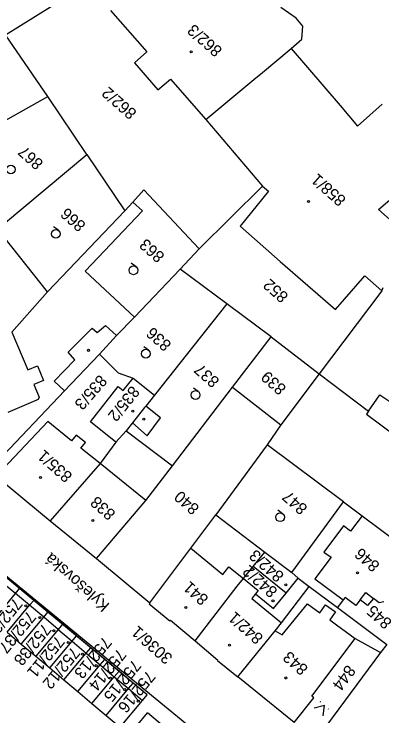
# Model space of a CAD drawing. Extents: x -496688 to -495455, y -1089309 to -1088026.
# Drawn here: x -496161.2 to -496098.1, y -1088339.8 to -1088219.5 of the extents above; entities that cross this region are included whole.
import ezdxf

# ---------------------------------------------------------------- set-up
doc = ezdxf.new("R2010")
doc.units = 0
for name, color, linetype in [('Vrstva 23', 7, 'Continuous'), ('Vrstva 52', 7, 'Continuous'), ('Vrstva 53', 7, 'Continuous'), ('Vrstva 55', 7, 'Continuous'), ('Vrstva 56', 7, 'Continuous'), ('Vrstva 57', 7, 'Continuous'), ('Vrstva 58', 7, 'Continuous'), ('Vrstva 59', 7, 'Continuous')]:
    doc.layers.add(name, color=color, linetype=linetype)

msp = doc.modelspace()

# ---------------------------------------------------------------- linework, layer by layer
at = {"layer": 'Vrstva 23'}
for p, q in [((-496112.79, -1088220.23), (-496115.42, -1088218.43)), ((-496144.6, -1088218.93), (-496138.4, -1088226.02)), ((-496111.62, -1088221.6), (-496112.79, -1088220.23)), ((-496111.79, -1088223.84), (-496111.62, -1088221.6)), ((-496113.66, -1088225.45), (-496111.79, -1088223.84)), ((-496118.91, -1088229.82), (-496113.66, -1088225.45)), ((-496113.66, -1088225.45), (-496105.26, -1088235.24)), ((-496128.26, -1088237.61), (-496119.69, -1088230.47)), ((-496119.69, -1088230.47), (-496118.91, -1088229.82)), ((-496134.32, -1088230.68), (-496128.26, -1088237.61)), ((-496105.26, -1088235.24), (-496102.26, -1088238.74)), ((-496102.26, -1088238.74), (-496098.04, -1088234.96)), ((-496128.26, -1088237.61), (-496118.54, -1088249.02)), ((-496098.65, -1088253.06), (-496092.09, -1088247.31)), ((-496118.54, -1088249.02), (-496117.55, -1088249.89)), ((-496092.23, -1088258.76), (-496098.65, -1088253.06)), ((-496098.08, -1088266.98), (-496100.99, -1088264.42)), ((-496098.08, -1088266.98), (-496097.87, -1088266.38)), ((-496147.73, -1088273.39), (-496146.88, -1088274.11)), ((-496146.88, -1088274.11), (-496145.47, -1088272.9)), ((-496145.47, -1088272.9), (-496143.57, -1088274.63)), ((-496161.51, -1088274.08), (-496158.8, -1088280.53)), ((-496146.52, -1088277.8), (-496143.57, -1088274.63)), ((-496150.7, -1088278.8), (-496151.86, -1088277.47)), ((-496148.95, -1088280.41), (-496146.52, -1088277.8)), ((-496158.8, -1088280.53), (-496157.14, -1088279.83)), ((-496154.26, -1088282.46), (-496150.7, -1088278.8)), ((-496142.42, -1088284.07), (-496140.75, -1088281.96)), ((-496140.75, -1088281.96), (-496137.09, -1088284.86)), ((-496156.09, -1088282.34), (-496157.75, -1088283.04)), ((-496157.75, -1088283.04), (-496156.84, -1088285.21)), ((-496152.52, -1088284.11), (-496154.26, -1088282.46)), ((-496148.07, -1088289.43), (-496143.32, -1088283.36)), ((-496143.32, -1088283.36), (-496142.42, -1088284.07)), ((-496157.03, -1088285.58), (-496162.2, -1088287.82)), ((-496137.09, -1088284.86), (-496138.57, -1088286.73)), ((-496100.39, -1088287.57), (-496098.46, -1088284.79)), ((-496098.46, -1088284.79), (-496093.56, -1088288.08)), ((-496138.76, -1088286.97), (-496140.84, -1088289.57)), ((-496138.57, -1088286.73), (-496138.76, -1088286.97)), ((-496136.04, -1088288.75), (-496138.57, -1088286.73)), ((-496100.39, -1088287.57), (-496100.74, -1088288.08)), ((-496100.74, -1088288.08), (-496095.56, -1088291.95)), ((-496155.37, -1088289.39), (-496164.02, -1088298.48)), ((-496151.28, -1088292.67), (-496155.37, -1088289.39)), ((-496143.68, -1088292.88), (-496148.07, -1088289.43)), ((-496140.84, -1088289.57), (-496141.93, -1088290.94)), ((-496140.84, -1088289.57), (-496138.33, -1088291.8)), ((-496150.49, -1088291.68), (-496151.28, -1088292.67)), ((-496148.9, -1088292.95), (-496150.49, -1088291.68)), ((-496141.93, -1088290.94), (-496143.68, -1088292.88)), ((-496149.69, -1088293.94), (-496148.9, -1088292.95)), ((-496146.4, -1088296.58), (-496149.69, -1088293.94)), ((-496146.4, -1088296.58), (-496154.95, -1088306.41)), ((-496164.23, -1088298.7), (-496154.95, -1088306.41)), ((-496147.01, -1088312.86), (-496138.54, -1088302.87)), ((-496101.47, -1088305.51), (-496103.46, -1088308.16)), ((-496101.47, -1088305.51), (-496092.02, -1088312.57)), ((-496154.95, -1088306.41), (-496147.01, -1088312.86)), ((-496103.46, -1088308.16), (-496104.69, -1088307.24)), ((-496137.88, -1088320.43), (-496130.83, -1088311.08)), ((-496120.16, -1088314.21), (-496118.15, -1088311.73)), ((-496118.15, -1088311.73), (-496113.5, -1088315.25)), ((-496108.02, -1088311.73), (-496106.81, -1088312.63)), ((-496106.81, -1088312.63), (-496109.56, -1088316.31)), ((-496125.37, -1088315.57), (-496124.3, -1088314.26)), ((-496124.3, -1088314.26), (-496121.81, -1088316.24)), ((-496121.81, -1088316.24), (-496120.16, -1088314.21)), ((-496114.51, -1088318.76), (-496120.16, -1088314.21)), ((-496113.5, -1088315.25), (-496112.44, -1088316.23)), ((-496160.91, -1088318.84), (-496163.33, -1088316.82)), ((-496122.92, -1088317.59), (-496121.81, -1088316.24)), ((-496121.81, -1088316.24), (-496119.27, -1088318.32)), ((-496114.51, -1088318.76), (-496112.44, -1088316.23)), ((-496109.56, -1088316.31), (-496104.72, -1088319.89)), ((-496160.91, -1088318.84), (-496160.21, -1088317.99)), ((-496130.12, -1088326.92), (-496122.92, -1088317.59)), ((-496119.27, -1088318.32), (-496119.73, -1088318.87)), ((-496164.73, -1088323.45), (-496160.91, -1088318.84)), ((-496158.49, -1088320.86), (-496160.91, -1088318.84)), ((-496119.73, -1088318.87), (-496120.38, -1088319.67)), ((-496119.73, -1088318.87), (-496116.67, -1088321.39)), ((-496116.67, -1088321.39), (-496114.51, -1088318.76)), ((-496104.41, -1088319.49), (-496104.72, -1088319.89)), ((-496102.56, -1088320.89), (-496104.41, -1088319.49)), ((-496101.83, -1088319.94), (-496100.85, -1088318.64)), ((-496158.49, -1088320.86), (-496157.78, -1088320.01)), ((-496137.88, -1088320.43), (-496138.01, -1088320.62)), ((-496138.01, -1088320.62), (-496134.44, -1088323.53)), ((-496115.16, -1088325.93), (-496110.83, -1088320.6)), ((-496110.83, -1088320.6), (-496108.74, -1088322.12)), ((-496108.74, -1088322.12), (-496107.74, -1088320.75)), ((-496107.74, -1088320.75), (-496106.03, -1088321.99)), ((-496101.83, -1088319.94), (-496102.56, -1088320.89)), ((-496100.53, -1088320.88), (-496101.83, -1088319.94)), ((-496099.52, -1088319.68), (-496100.53, -1088320.88)), ((-496098.57, -1088320.43), (-496099.52, -1088319.68)), ((-496097.76, -1088320.27), (-496098.57, -1088320.43)), ((-496162.32, -1088325.48), (-496158.49, -1088320.86)), ((-496156.07, -1088322.89), (-496158.49, -1088320.86)), ((-496159.9, -1088327.5), (-496156.07, -1088322.89)), ((-496156.07, -1088322.89), (-496155.35, -1088322.02)), ((-496153.6, -1088325.01), (-496156.07, -1088322.89)), ((-496106.21, -1088322.23), (-496107.03, -1088323.37)), ((-496152.84, -1088324.11), (-496153.6, -1088325.01)), ((-496134.44, -1088323.53), (-496134.33, -1088323.4)), ((-496134.33, -1088323.4), (-496130.12, -1088326.92)), ((-496107.03, -1088323.37), (-496105.88, -1088324.2)), ((-496162.32, -1088325.48), (-496159.9, -1088327.5)), ((-496153.6, -1088325.01), (-496157.42, -1088329.57)), ((-496153.6, -1088325.01), (-496151.21, -1088327.02)), ((-496122.78, -1088333.12), (-496116.38, -1088325.22)), ((-496116.38, -1088325.22), (-496115.16, -1088325.93)), ((-496151.21, -1088327.02), (-496150.42, -1088326.11)), ((-496110.07, -1088336.41), (-496102.69, -1088326.52)), ((-496159.9, -1088327.5), (-496157.42, -1088329.57)), ((-496155.02, -1088331.59), (-496151.21, -1088327.02)), ((-496151.21, -1088327.02), (-496148.78, -1088329.06)), ((-496130.12, -1088326.92), (-496126.19, -1088330.23)), ((-496152.6, -1088333.64), (-496148.78, -1088329.06)), ((-496148.78, -1088329.06), (-496147.99, -1088328.13)), ((-496148.78, -1088329.06), (-496146.38, -1088331.07)), ((-496157.42, -1088329.57), (-496155.02, -1088331.59)), ((-496146.38, -1088331.07), (-496145.58, -1088330.13)), ((-496126.19, -1088330.23), (-496126.29, -1088330.34)), ((-496126.29, -1088330.34), (-496123.28, -1088332.72)), ((-496155.02, -1088331.59), (-496152.6, -1088333.64)), ((-496150.21, -1088335.65), (-496146.38, -1088331.07)), ((-496146.38, -1088331.07), (-496143.97, -1088333.1)), ((-496143.97, -1088333.1), (-496143.15, -1088332.15)), ((-496123.28, -1088332.72), (-496122.78, -1088333.12)), ((-496152.6, -1088333.64), (-496150.21, -1088335.65)), ((-496147.79, -1088337.68), (-496143.97, -1088333.1)), ((-496143.97, -1088333.1), (-496141.55, -1088335.13)), ((-496113.14, -1088340.92), (-496122.78, -1088333.12)), ((-496145.37, -1088339.71), (-496141.55, -1088335.13)), ((-496141.55, -1088335.13), (-496140.72, -1088334.17)), ((-496141.55, -1088335.13), (-496139.15, -1088337.15)), ((-496150.21, -1088335.65), (-496147.79, -1088337.68)), ((-496139.15, -1088337.15), (-496138.32, -1088336.17)), ((-496142.97, -1088341.74), (-496139.15, -1088337.15)), ((-496113.14, -1088340.92), (-496109.74, -1088336.7)), ((-496109.74, -1088336.7), (-496110.07, -1088336.41)), ((-496147.79, -1088337.68), (-496145.37, -1088339.71)), ((-496145.37, -1088339.71), (-496142.97, -1088341.74))]:
    msp.add_line(p, q, dxfattribs=at)
for points in [[(-496138.4, -1088226.02), (-496140.48, -1088227.9), (-496136.51, -1088232.52), (-496134.32, -1088230.68)], [(-496117.55, -1088249.89), (-496122.37, -1088255.87), (-496115.51, -1088261.93), (-496106.03, -1088270.19), (-496100.99, -1088264.42)], [(-496170.807, -1088309.208), (-496138.345, -1088336.158)], [(-496142.065, -1088343.835), (-496138.252, -1088339.268)], [(-496104.453, -1088367.769), (-496138.252, -1088339.268)]]:
    msp.add_lwpolyline(points, dxfattribs=at)
at = {"layer": 'Vrstva 52'}
for p, q in [((-496151.86, -1088277.47), (-496147.73, -1088273.39)), ((-496138.33, -1088291.8), (-496136.04, -1088288.75)), ((-496138.54, -1088302.87), (-496146.4, -1088296.58)), ((-496130.83, -1088311.08), (-496125.37, -1088315.57)), ((-496100.85, -1088318.64), (-496099.52, -1088319.68)), ((-496120.38, -1088319.67), (-496115.28, -1088323.86)), ((-496105.88, -1088324.2), (-496102.69, -1088326.52))]:
    msp.add_line(p, q, dxfattribs=at)
at = {"layer": 'Vrstva 53'}
msp.add_lwpolyline([(-496188.02, -1088275.91), (-496175.34, -1088305.32), (-496115.85, -1088354.08), (-496107.5, -1088361.45)], dxfattribs=at)
at = {"layer": 'Vrstva 55'}
for p, q in [((-496162.6, -1088223.08), (-496138.52, -1088208.12)), ((-496155.35, -1088233.68), (-496162.6, -1088223.08)), ((-496170.44, -1088242.08), (-496155.35, -1088233.68)), ((-496148.66, -1088243.61), (-496155.35, -1088233.68)), ((-496162.94, -1088255.53), (-496148.66, -1088243.61)), ((-496148.66, -1088243.61), (-496142.14, -1088253.24)), ((-496138.88, -1088249.67), (-496140.78, -1088251.76)), ((-496129.39, -1088259.8), (-496138.88, -1088249.67)), ((-496129.39, -1088259.8), (-496118.54, -1088249.02)), ((-496140.78, -1088251.76), (-496142.14, -1088253.24)), ((-496140.78, -1088251.76), (-496139.1, -1088253.29)), ((-496142.14, -1088253.24), (-496155.43, -1088267.13)), ((-496139.1, -1088253.29), (-496148.98, -1088263.63)), ((-496155.43, -1088267.13), (-496163.98, -1088256.4)), ((-496132.65, -1088263.27), (-496129.39, -1088259.8)), ((-496148.98, -1088263.63), (-496140.49, -1088271.46)), ((-496140.49, -1088271.46), (-496132.65, -1088263.27)), ((-496124.69, -1088269.21), (-496132.65, -1088263.27)), ((-496155.43, -1088267.13), (-496161.51, -1088274.08)), ((-496098.08, -1088266.98), (-496108.86, -1088281.21)), ((-496124.69, -1088269.21), (-496137.09, -1088284.86)), ((-496117.05, -1088274.85), (-496124.69, -1088269.21)), ((-496143.57, -1088274.63), (-496140.49, -1088271.46)), ((-496123.68, -1088283.47), (-496117.05, -1088274.85)), ((-496117.05, -1088274.85), (-496108.86, -1088281.21)), ((-496146.52, -1088277.8), (-496143.3, -1088281.03)), ((-496152.52, -1088284.11), (-496148.95, -1088280.41)), ((-496143.3, -1088281.03), (-496140.75, -1088281.96)), ((-496108.86, -1088281.21), (-496115.43, -1088289.93)), ((-496108.86, -1088281.21), (-496100.39, -1088287.57)), ((-496133.98, -1088296.93), (-496123.68, -1088283.47)), ((-496123.68, -1088283.47), (-496115.43, -1088289.93)), ((-496165.22, -1088297.46), (-496152.52, -1088284.11)), ((-496115.43, -1088289.93), (-496117.73, -1088293.34)), ((-496141.93, -1088290.94), (-496133.98, -1088296.93)), ((-496143.68, -1088292.88), (-496146.4, -1088296.58)), ((-496117.73, -1088293.34), (-496126.53, -1088305.37)), ((-496104.68, -1088303.11), (-496117.73, -1088293.34)), ((-496138.54, -1088302.87), (-496133.98, -1088296.93)), ((-496113.5, -1088315.25), (-496104.68, -1088303.11)), ((-496104.68, -1088303.11), (-496101.47, -1088305.51)), ((-496130.83, -1088311.08), (-496126.53, -1088305.37)), ((-496126.53, -1088305.37), (-496118.15, -1088311.73)), ((-496147.01, -1088312.86), (-496137.88, -1088320.43)), ((-496160.21, -1088317.99), (-496162.63, -1088315.98)), ((-496112.44, -1088316.23), (-496110.54, -1088317.61)), ((-496157.78, -1088320.01), (-496160.21, -1088317.99)), ((-496115.28, -1088323.86), (-496110.54, -1088317.61)), ((-496110.54, -1088317.61), (-496105.72, -1088321.22)), ((-496155.35, -1088322.02), (-496157.78, -1088320.01)), ((-496104.72, -1088319.89), (-496105.72, -1088321.22)), ((-496105.72, -1088321.22), (-496097.26, -1088327.56)), ((-496152.84, -1088324.11), (-496155.35, -1088322.02)), ((-496150.42, -1088326.11), (-496152.84, -1088324.11)), ((-496116.38, -1088325.22), (-496115.28, -1088323.86)), ((-496147.99, -1088328.13), (-496150.42, -1088326.11)), ((-496102.69, -1088326.52), (-496098.3, -1088328.96)), ((-496097.26, -1088327.56), (-496098.3, -1088328.96)), ((-496145.58, -1088330.13), (-496147.99, -1088328.13)), ((-496098.3, -1088328.96), (-496107.57, -1088341.47)), ((-496143.15, -1088332.15), (-496145.58, -1088330.13)), ((-496140.72, -1088334.17), (-496143.15, -1088332.15)), ((-496138.32, -1088336.17), (-496140.72, -1088334.17))]:
    msp.add_line(p, q, dxfattribs=at)
at = {"layer": 'Vrstva 56'}
for p, q in [((-496157.14, -1088279.83), (-496156.09, -1088282.34)), ((-496156.84, -1088285.21), (-496157.03, -1088285.58)), ((-496104.69, -1088307.24), (-496108.02, -1088311.73)), ((-496106.03, -1088321.99), (-496106.21, -1088322.23))]:
    msp.add_line(p, q, dxfattribs=at)
at = {"layer": 'Vrstva 58'}
for p, q in [((-496153.551, -1088256.606), (-496154.357, -1088256.015)), ((-496140.24, -1088262.849), (-496141.046, -1088262.258)), ((-496138.118, -1088277.137), (-496138.924, -1088276.546)), ((-496129.579, -1088284.222), (-496130.385, -1088283.631)), ((-496115.103, -1088305.164), (-496115.909, -1088304.573)), ((-496108.574, -1088337.452), (-496108.649, -1088337.386)), ((-496107.225, -1088338.644), (-496107.3, -1088338.578))]:
    msp.add_line(p, q, dxfattribs=at)
msp.add_lwpolyline([(-496108.182, -1088339.801), (-496107.937, -1088338.015), (-496109.68, -1088338.476)], dxfattribs=at)
for centre in [(-496161.689, -1088246.183), (-496153.994, -1088257.211), (-496140.683, -1088263.454), (-496138.561, -1088277.742), (-496130.022, -1088284.827), (-496115.546, -1088305.769)]:
    msp.add_circle(centre, 0.75, dxfattribs=at)
at = {"layer": 'Vrstva 59'}
for centre in [(-496130.795, -1088226.002), (-496110.661, -1088251.665), (-496148.37, -1088277.169), (-496140.769, -1088287.588), (-496138.894, -1088288.943), (-496156.597, -1088298.945), (-496147.642, -1088306.342), (-496102.28, -1088315.279), (-496114.569, -1088317.362), (-496159.11, -1088320.934), (-496116.755, -1088320.071), (-496131.708, -1088321.241), (-496156.715, -1088322.965), (-496154.32, -1088325.205), (-496151.874, -1088327.236), (-496124.21, -1088327.701), (-496149.427, -1088329.216), (-496147.084, -1088331.195), (-496144.637, -1088333.33), (-496114.569, -1088333.303), (-496142.138, -1088335.31), (-496139.847, -1088337.289)]:
    msp.add_circle(centre, 0.175, dxfattribs=at)

# ---------------------------------------------------------------- texts
at = {"layer": 'Vrstva 57'}
for s, rotation, p in [('862/3', 138.47617, (-496125.311, -1088225.579)), ('862/2', 138.47617, (-496139.975, -1088236.295)), ('867', 138.47617, (-496155.99, -1088244.93)), ('858/1', 138.47617, (-496104.096, -1088251.174)), ('866', 138.47617, (-496148.71, -1088255.543)), ('863', 138.47617, (-496135.196, -1088260.845)), ('852', 138.47617, (-496113.976, -1088267.716)), ('836', 138.47617, (-496134.028, -1088276.009)), ('837', 138.47617, (-496125.801, -1088282.26)), ('839', 138.47617, (-496114.346, -1088283.51)), ('835/3', 228.9837, (-496146.525, -1088281.217)), ('835/2', 231.34019, (-496141.005, -1088283.094)), ('835/1', 138.47617, (-496151.003, -1088298.514)), ('840', 138.47617, (-496129.238, -1088304.035)), ('838', 138.47617, (-496143.609, -1088304.973)), ('847', 138.47617, (-496110.701, -1088304.035)), ('846', 138.47617, (-496098.309, -1088313.829)), ('Kylešovská', 138.47617, (-496144.633, -1088320.697)), ('842/3', 138.47617, (-496114.717, -1088315.593)), ('842/2', 138.47617, (-496115.835, -1088318.25)), ('841', 138.47617, (-496127.676, -1088319.559)), ('752/36', 230.66315, (-496161.093, -1088319.443)), ('842/1', 138.47617, (-496118.283, -1088326.224)), ('845', 138.47617, (-496096.226, -1088323.622)), ('752/37', 230.66315, (-496158.75, -1088321.683)), ('752/38', 230.66315, (-496156.146, -1088323.819)), ('3036/1', 138.47617, (-496133.807, -1088329.649)), ('752/11', 230.66315, (-496153.856, -1088325.903)), ('752/13', 230.66315, (-496145.787, -1088326.06)), ('752/12', 230.66315, (-496151.201, -1088327.831)), ('752/14', 230.66315, (-496143.288, -1088328.143)), ('843', 138.47617, (-496110.597, -1088331.541)), ('752/15', 230.66315, (-496140.737, -1088330.018)), ('844', 233.46129, (-496104.037, -1088330.915)), ('752/16', 230.66315, (-496138.29, -1088331.893))]:
    msp.add_text(s, height=2, rotation=rotation, dxfattribs=at).set_placement(p)

doc.saveas('drawing.dxf')
